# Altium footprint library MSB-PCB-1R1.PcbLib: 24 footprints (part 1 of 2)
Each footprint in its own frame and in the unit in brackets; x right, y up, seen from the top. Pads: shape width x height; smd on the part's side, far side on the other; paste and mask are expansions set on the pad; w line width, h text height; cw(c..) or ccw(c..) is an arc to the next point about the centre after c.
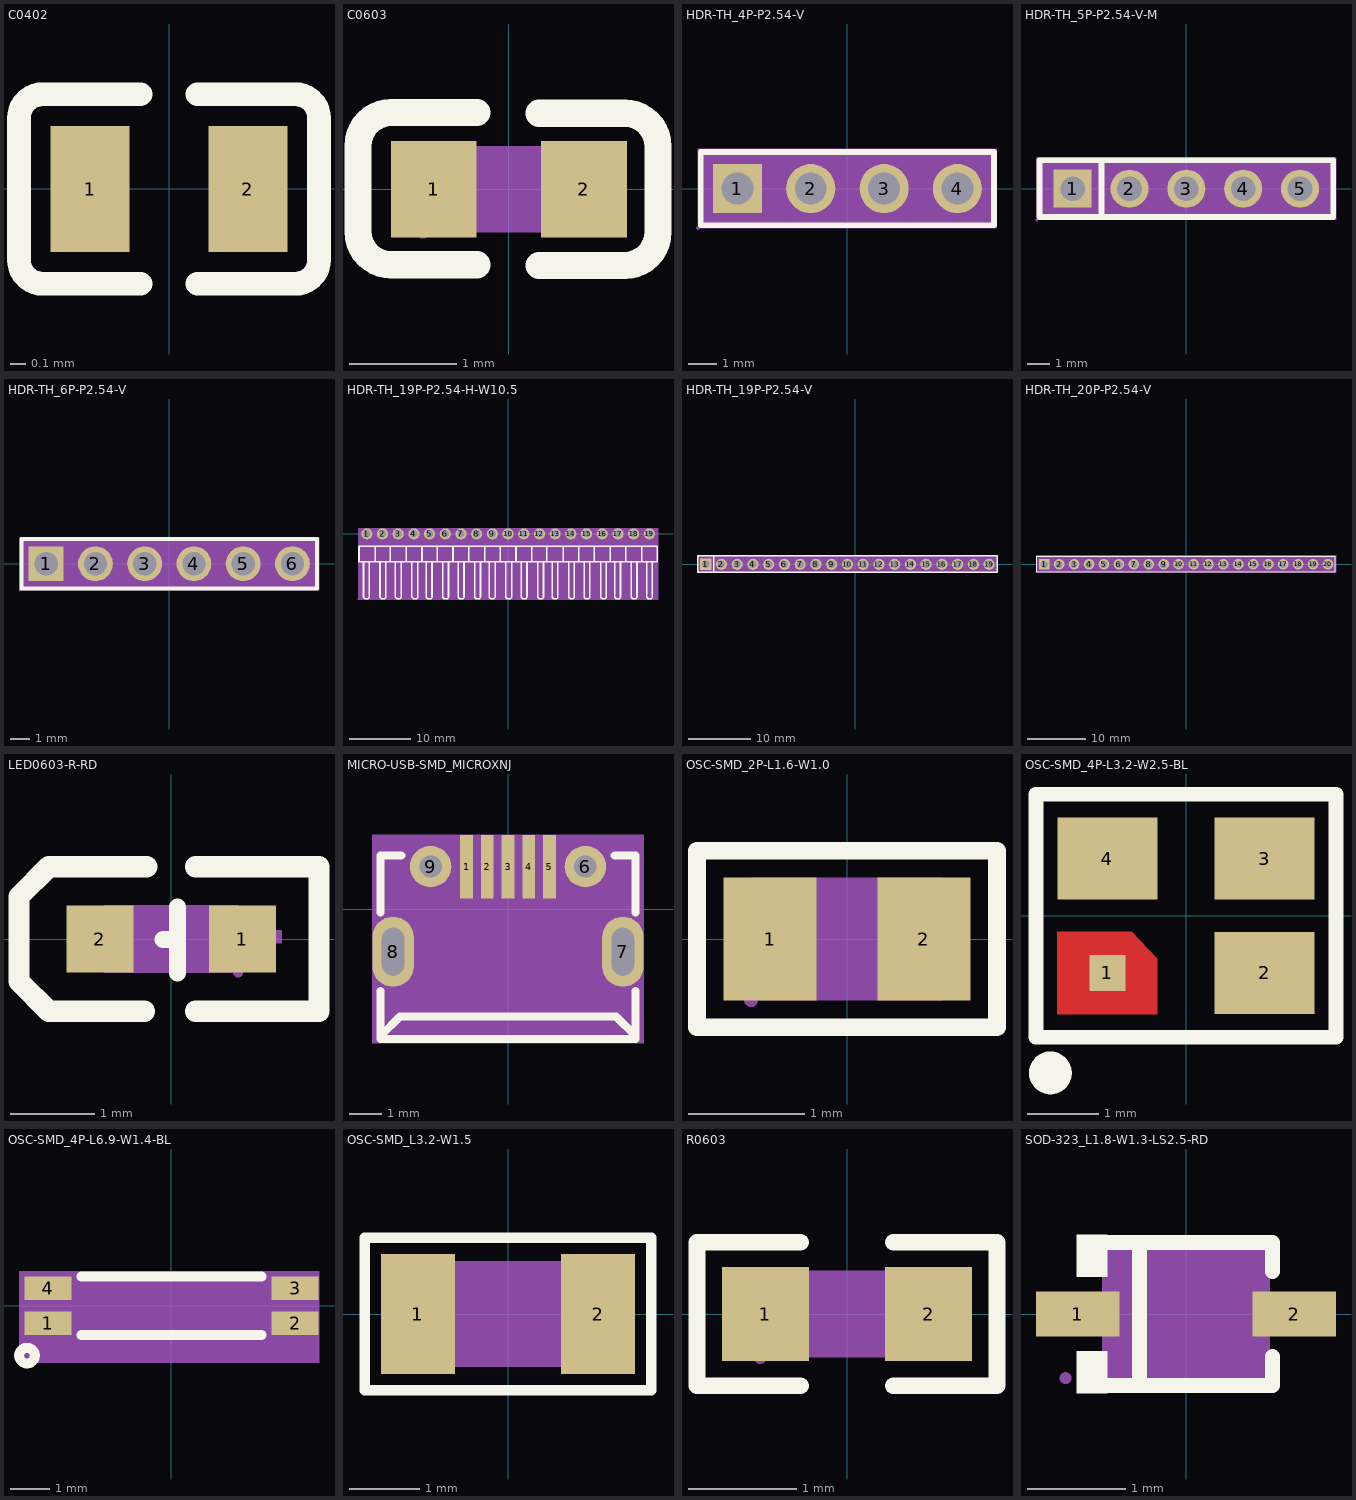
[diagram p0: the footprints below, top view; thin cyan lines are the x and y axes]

## C0402 [mm]
pads (2):
  rect 0.5x0.8 smd: 1(-0.5,0) 2(0.5,0)
Top Overlay:
  lines w0.15: -0.18,-0.6 -0.8,-0.6 cw(c-0.8,-0.45) -0.95,-0.45 -0.95,-0.4 -0.95,0.4 -0.95,0.45 cw(c-0.8,0.45) -0.8,0.6 -0.18,0.6 ; 0.18,-0.6 0.8,-0.6 ccw(c0.8,-0.45) 0.95,-0.45 0.95,-0.4 0.95,0.4 0.95,0.45 ccw(c0.8,0.45) 0.8,0.6 0.18,0.6

## C0603 [mm]
pads (2):
  rect 0.8x0.9 smd: 1(-0.7,0) 2(0.7,0)
Top Overlay:
  lines w0.254: -0.296,-0.704 -1.096,-0.704 cw(c-1.096,-0.394) -1.406,-0.394 -1.405,0.406 cw(c-1.096,0.406) -1.096,0.715 -0.296,0.715 ; 0.28,-0.71 1.08,-0.71 ccw(c1.08,-0.4) 1.39,-0.4 1.39,0.4 ccw(c1.08,0.4) 1.08,0.71 0.28,0.71
Mechanical 4:
  region: -0.8,-0.4 -0.8,0.4 0.8,0.4 0.8,-0.4
Mechanical 5:
  region: -0.8,-0.4 -0.8,0.4 -0.5,0.4 -0.5,-0.4
  region: 0.8,-0.4 0.8,0.4 0.5,0.4 0.5,-0.4
Mechanical 6:
  circle w0.06: c-0.8,-0.4 r0.03

## HDR-TH_4P-P2.54-V [mm]
pads (4):
  rect 1.7x1.7 hole 1.1: 1(-3.81,0)
  round 1.7 hole 1.1: 2(-1.27,0) 3(1.27,0) 4(3.81,0)
Top Overlay:
  lines w0.203: -5.08,-1.27 -5.08,1.27 -3.175,1.27 5.08,1.27 5.08,-1.27 -5.08,-1.27
Mechanical 4:
  region: -5.182,1.372 5.182,1.372 5.182,-1.372 -5.182,-1.372
Mechanical 5:
  circle w0.45: c3.81,0 r0.225
  circle w0.45: c1.27,0 r0.225
  circle w0.45: c-1.27,0 r0.225
  circle w0.45: c-3.81,0 r0.225
Mechanical 6:
  circle w0.06: c-5.182,-1.372 r0.03

## HDR-TH_5P-P2.54-V-M [mm]
pads (5):
  rect 1.7x1.7 hole 1.1: 1(-5.08,0)
  round 1.7 hole 1.1: 2(-2.54,0) 3(0,0) 4(2.54,0) 5(5.08,0)
Top Overlay:
  lines w0.254: -3.786,-1.27 -3.786,1.27 ; -6.56,-1.27 -6.56,1.27 6.56,1.27 6.56,-1.27 -6.56,-1.27
Mechanical 4:
  region: -6.687,1.397 6.687,1.397 6.687,-1.397 -6.687,-1.397
Mechanical 5:
  circle w0.45: c5.08,0 r0.225
  circle w0.45: c2.54,0 r0.225
  circle w0.45: c0,0 r0.225
  circle w0.45: c-2.54,0 r0.225
  circle w0.45: c-5.08,0 r0.225
Mechanical 6:
  circle w0.06: c-6.687,-1.397 r0.03

## HDR-TH_6P-P2.54-V [mm]
pads (6):
  rect 1.8x1.8 hole 1.2: 1(-6.35,0)
  round 1.8 hole 1.2: 2(-3.81,0) 3(-1.27,0) 4(1.27,0) 5(3.81,0) 6(6.35,0)
Top Overlay:
  lines w0.203: -7.62,-1.27 7.62,-1.27 7.62,1.27 -5.715,1.27 -7.62,1.27 -7.62,-1.27
Mechanical 4:
  region: -7.722,1.372 7.722,1.372 7.722,-1.372 -7.722,-1.372
Mechanical 5:
  circle w0.5: c-6.35,0 r0.25
  circle w0.5: c-3.81,0 r0.25
  circle w0.5: c-1.27,0 r0.25
  circle w0.5: c1.27,0 r0.25
  circle w0.5: c3.81,0 r0.25
  circle w0.5: c6.35,0 r0.25
Mechanical 6:
  circle w0.06: c-7.722,-1.372 r0.03

## HDR-TH_19P-P2.54-H-W10.5 [mm]
pads (19):
  round 1.8 hole 1.2: 1(-22.86,0) 2(-20.32,0) 3(-17.78,0) 4(-15.24,0) 5(-12.7,0) 6(-10.16,0) 7(-7.62,0) 8(-5.08,0) 9(-2.54,0) 10(0,0) 11(2.54,0) 12(5.08,0) 13(7.62,0) 14(10.16,0) 15(12.7,0) 16(15.24,0) 17(17.78,0) 18(20.32,0) 19(22.86,0)
Top Overlay:
  lines w0.254: -23.402,-4.5 -23.402,-10.264 -23.166,-10.5 -22.692,-10.5 -22.479,-10.287 -22.479,-4.5 ; -21.511,-4.5 -21.511,-2 ; -20.73,-4.5 -20.73,-10.264 -20.494,-10.5 ; -20.495,-10.5 -20.02,-10.5 -19.807,-10.287 -19.807,-6.54 -19.807,-4.501 ; -19.073,-4.5 -19.073,-2 ; -18.23,-4.5 -18.23,-10.264 -17.994,-10.5 -17.52,-10.5 -17.307,-10.287 -17.307,-4.5 ; -16.499,-4.5 -16.499,-2 ; -15.558,-4.5 -15.558,-10.264 -15.322,-10.5 -14.848,-10.5 -14.635,-10.287 -14.635,-4.5 ; -13.925,-4.5 -13.925,-2 ; -13.23,-4.5 -13.23,-10.264 -12.994,-10.5 -12.52,-10.5 -12.307,-10.287 -12.307,-4.5 ; -11.487,-4.5 -11.487,-2 ; -10.558,-4.5 -10.558,-10.264 -10.322,-10.5 -9.848,-10.5 -9.635,-10.287 -9.635,-6.541 -9.635,-4.501 ; -8.913,-4.5 -8.913,-2 ; -8.058,-4.5 -8.058,-10.264 -7.822,-10.5 -7.348,-10.5 -7.135,-10.287 -7.135,-4.5 ; -6.373,-4.5 -6.373,-2 ; -5.386,-4.5 -5.386,-10.264 -5.15,-10.5 -4.676,-10.5 -4.463,-10.287 -4.463,-4.5 ; -3.765,-4.5 -3.765,-2 ; -3.03,-4.5 -3.03,-10.264 -2.794,-10.5 -2.32,-10.5 -2.107,-10.287 -2.107,-4.5 ; -1.293,-4.5 -1.293,-2 ; -0.358,-4.5 -0.358,-10.264 -0.122,-10.5 0.352,-10.5 0.565,-10.287 0.565,-6.542 0.565,-4.5 ; 1.281,-4.5 1.281,-2 ; 2.142,-4.5 2.142,-10.264 2.378,-10.5 2.852,-10.5 3.065,-10.287 3.065,-4.5 ; 3.855,-4.5 3.855,-2 ; 4.814,-4.5 4.814,-10.264 5.05,-10.5 5.524,-10.5 5.737,-10.287 5.737,-4.5 ; 6.293,-4.5 6.293,-2 ; 7.142,-4.5 7.142,-10.264 7.378,-10.5 7.852,-10.5 8.065,-10.287 8.065,-4.5 ; 8.901,-4.5 8.901,-2 ; 9.814,-4.5 9.814,-10.264 10.05,-10.5 ; 10.049,-10.5 10.524,-10.5 10.737,-10.287 10.737,-6.54 10.737,-4.501 ; 11.475,-4.5 11.475,-2 ; 12.314,-4.5 12.314,-10.264 12.55,-10.5 13.024,-10.5 13.237,-10.287 13.237,-4.5 ; 13.981,-4.5 13.981,-2 ; 14.986,-4.5 14.986,-10.264 15.222,-10.5 15.697,-10.5 15.91,-10.287 15.91,-4.5 ; 16.555,-4.5 16.555,-2 ; 17.27,-4.5 17.27,-10.264 17.506,-10.5 17.98,-10.5 18.193,-10.287 18.193,-4.5 ; 19.027,-4.5 19.027,-2 ; 19.942,-4.5 19.942,-10.264 20.178,-10.5 ; 20.865,-4.501 20.865,-6.54 ; 21.635,-4.5 21.635,-2 ; 22.442,-4.5 22.442,-10.264 22.678,-10.5 23.152,-10.5 23.365,-10.287 23.365,-4.5 ; 24.13,-4.5 -24.13,-4.5 -24.13,-2 24.13,-2 ; 24.141,-4.5 24.141,-2 ; 20.652,-10.5 20.177,-10.5 20.652,-10.5 ; 20.652,-10.5 20.865,-10.287 ; 20.652,-10.5 20.865,-10.287 ; 20.865,-10.287 20.865,-6.54 ; 20.865,-10.287 20.865,-6.54
Mechanical 4:
  region: -24.257,0.9 24.268,0.9 24.268,-10.627 -24.257,-10.627
Mechanical 5:
  circle w0.5: c-22.86,0 r0.25
  circle w0.5: c-20.32,0 r0.25
  circle w0.5: c-17.78,0 r0.25
  circle w0.5: c-15.24,0 r0.25
  circle w0.5: c-12.7,0 r0.25
  circle w0.5: c-10.16,0 r0.25
  circle w0.5: c-7.62,0 r0.25
  circle w0.5: c-5.08,0 r0.25
  circle w0.5: c-2.54,0 r0.25
  circle w0.5: c0,0 r0.25
  circle w0.5: c2.54,0 r0.25
  circle w0.5: c5.08,0 r0.25
  circle w0.5: c7.62,0 r0.25
  circle w0.5: c10.16,0 r0.25
  circle w0.5: c12.7,0 r0.25
  circle w0.5: c15.24,0 r0.25
  circle w0.5: c17.78,0 r0.25
  circle w0.5: c20.32,0 r0.25
  circle w0.5: c22.86,0 r0.25
Mechanical 6:
  circle w0.06: c-24.257,-10.627 r0.03

## HDR-TH_19P-P2.54-V [mm]
pads (19):
  rect 1.8x1.8 hole 1.2: 1(-24.13,0)
  round 1.8 hole 1.2: 2(-21.59,0) 3(-19.05,0) 4(-16.51,0) 5(-13.97,0) 6(-11.43,0) 7(-8.89,0) 8(-6.35,0) 9(-3.81,0) 10(-1.27,0) 11(1.27,0) 12(3.81,0) 13(6.35,0) 14(8.89,0) 15(11.43,0) 16(13.97,0) 17(16.51,0) 18(19.05,0) 19(21.59,0)
Top Overlay:
  lines w0.203: -22.86,-1.27 -22.86,1.397 ; -25.4,-1.27 -25.4,1.397 22.86,1.397 22.86,0.635 22.86,-1.27 -25.4,-1.27
Mechanical 4:
  region: -25.502,1.499 22.86,1.499 22.86,-1.372 -25.502,-1.372
Mechanical 5:
  circle w0.5: c21.59,0 r0.25
  circle w0.5: c19.05,0 r0.25
  circle w0.5: c16.51,0 r0.25
  circle w0.5: c13.97,0 r0.25
  circle w0.5: c11.43,0 r0.25
  circle w0.5: c8.89,0 r0.25
  circle w0.5: c6.35,0 r0.25
  circle w0.5: c3.81,0 r0.25
  circle w0.5: c1.27,0 r0.25
  circle w0.5: c-1.27,0 r0.25
  circle w0.5: c-3.81,0 r0.25
  circle w0.5: c-6.35,0 r0.25
  circle w0.5: c-8.89,0 r0.25
  circle w0.5: c-11.43,0 r0.25
  circle w0.5: c-13.97,0 r0.25
  circle w0.5: c-16.51,0 r0.25
  circle w0.5: c-19.05,0 r0.25
  circle w0.5: c-21.59,0 r0.25
  circle w0.5: c-24.13,0 r0.25
Mechanical 6:
  circle w0.06: c-25.502,-1.372 r0.03

## HDR-TH_20P-P2.54-V [mm]
pads (20):
  rect 1.8x1.8 hole 1.2: 1(-24.13,0)
  round 1.8 hole 1.2: 2(-21.59,0) 3(-19.05,0) 4(-16.51,0) 5(-13.97,0) 6(-11.43,0) 7(-8.89,0) 8(-6.35,0) 9(-3.81,0) 10(-1.27,0) 11(1.27,0) 12(3.81,0) 13(6.35,0) 14(8.89,0) 15(11.43,0) 16(13.97,0) 17(16.51,0) 18(19.05,0) 19(21.59,0) 20(24.13,0)
Top Overlay:
  lines w0.203: -25.4,-1.27 25.4,-1.27 25.4,1.27 25.4,1.397 -25.4,1.397 -25.4,-1.27
Mechanical 4:
  region: -25.502,1.499 25.502,1.499 25.502,-1.372 -25.502,-1.372
Mechanical 5:
  circle w0.5: c-24.13,0 r0.25
  circle w0.5: c-21.59,0 r0.25
  circle w0.5: c-19.05,0 r0.25
  circle w0.5: c-16.51,0 r0.25
  circle w0.5: c-13.97,0 r0.25
  circle w0.5: c-11.43,0 r0.25
  circle w0.5: c-8.89,0 r0.25
  circle w0.5: c-6.35,0 r0.25
  circle w0.5: c-3.81,0 r0.25
  circle w0.5: c-1.27,0 r0.25
  circle w0.5: c1.27,0 r0.25
  circle w0.5: c3.81,0 r0.25
  circle w0.5: c6.35,0 r0.25
  circle w0.5: c8.89,0 r0.25
  circle w0.5: c11.43,0 r0.25
  circle w0.5: c13.97,0 r0.25
  circle w0.5: c16.51,0 r0.25
  circle w0.5: c19.05,0 r0.25
  circle w0.5: c21.59,0 r0.25
  circle w0.5: c24.13,0 r0.25
Mechanical 6:
  circle w0.06: c-25.502,-1.372 r0.03

## LED0603-R-RD [mm]
pads (2):
  rect 0.8x0.8 smd: 1(0.851,0) 2(-0.851,0)
Top Overlay:
  lines w0.203: -0.099,-0.008 0.076,-0.008 ; 0.076,-0.406 0.076,0.381
  lines w0.254: -0.318,-0.864 -1.46,-0.864 -1.816,-0.508 -1.816,0.508 -1.46,0.864 -0.292,0.864 ; 0.292,-0.864 1.765,-0.864 1.765,0.864 0.292,0.864
Mechanical 4:
  region: -0.8,0.4 0.8,0.4 0.8,-0.4 -0.8,-0.4
Mechanical 5:
  region: 0.8,0.4 0.8,-0.4 0.5,-0.4 0.5,0.4
  region: -0.8,-0.4 -0.8,0.4 -0.5,0.4 -0.5,-0.4
Mechanical 6:
  circle w0.06: c0.8,-0.4 r0.03
Mechanical 15:
  region: 0.66,0.102 1.321,0.102 1.321,-0.051 0.66,-0.051
  region: 0.936,-0.275 0.936,0.385 1.088,0.385 1.088,-0.275
  region: -1.193,0.05 -0.533,0.05 -0.533,-0.103 -1.193,-0.103

## MICRO-USB-SMD_MICROXNJ [mm]
pads (9):
  rect 0.4x2 smd mask+0: 1(-1.3,1.327) 2(-0.65,1.327) 3(0,1.327) 4(0.65,1.327) 5(1.3,1.327)
  round 1.3 hole 0.7: 6(2.425,1.335) 9(-2.425,1.335)
  oval 1.3x2.2 hole 0.7 slot 1.5 at 90 deg: 7(3.6,-1.335) 8(-3.6,-1.335)
Top Overlay:
  lines w0.254: -4,-4.073 4,-4.073 4,-2.57 ; -4,-4.052 -4,-2.57 ; -4,-0.1 -4,1.677 -3.344,1.677 ; -3.97,-4.052 -3.97,-3.953 -3.38,-3.363 3.39,-3.363 3.98,-3.953 3.98,-4.073 ; 3.344,1.677 4,1.677 4,-0.1
Mechanical 4:
  region: -4.25,2.328 4.25,2.328 4.25,-4.2 -4.25,-4.2
Mechanical 5:
  region: 1.1,2.327 1.5,2.327 1.5,0.327 1.1,0.327
  region: 0.45,2.327 0.85,2.327 0.85,0.327 0.45,0.327
  region: -0.2,2.327 0.2,2.327 0.2,0.327 -0.2,0.327
  region: -0.85,2.327 -0.45,2.327 -0.45,0.327 -0.85,0.327
  region: -1.5,2.327 -1.1,2.327 -1.1,0.327 -1.5,0.327

## OSC-SMD_2P-L1.6-W1.0 [mm]
pads (2):
  rect 0.8x1.06 smd: 1(-0.66,0) 2(0.66,0)
Top Overlay:
  lines w0.152: -1.289,-0.759 1.289,-0.759 1.289,0.759 -1.289,0.759 -1.289,-0.759
Mechanical 4:
  region: -0.825,-0.525 -0.825,0.525 0.825,0.525 0.825,-0.525
Mechanical 5:
  region: 0.36,-0.43 0.36,0.43 0.76,0.43 0.76,-0.43
  region: -0.36,-0.43 -0.36,0.43 -0.76,0.43 -0.76,-0.43
Mechanical 6:
  circle w0.06: c-0.825,-0.525 r0.03

## OSC-SMD_4P-L3.2-W2.5-BL [mm]
pads (4):
  rect 0.508x0.508 smd: 1(-1.1,-0.8)
  rect 1.4x1.15 smd: 2(1.1,-0.8) 3(1.1,0.8) 4(-1.1,0.8)
Top Layer:
  region: -1.8,-0.225 -0.762,-0.225 -0.4,-0.604 -0.4,-1.375 -1.8,-1.375
Top Overlay:
  lines w0.203: -2.1,-1.7 -2.1,1.7 2.1,1.7 2.1,-1.7 -2.1,-1.7
  lines w0.3: -1.9,-2.05 ccw(c-1.899,-2.2) -1.897,-2.05
Top Paste:
  region: -1.8,-0.225 -0.762,-0.225 -0.4,-0.604 -0.4,-1.375 -1.8,-1.375
Top Solder:
  region: -1.8,-0.225 -0.762,-0.225 -0.4,-0.604 -0.4,-1.375 -1.8,-1.375

## OSC-SMD_4P-L6.9-W1.4-BL [mm]
pads (4):
  rect 1.2x0.6 smd: 1(-3.15,-0.45) 2(3.15,-0.45) 3(3.15,0.45) 4(-3.15,0.45)
Top Overlay:
  circle w0.254: c-3.683,-1.27 r0.2
  lines w0.254: -2.3,-0.75 2.3,-0.75 ; -2.3,0.75 2.3,0.75
Mechanical 4:
  region: -3.886,0.877 3.759,0.877 3.759,-1.448 -3.886,-1.448
Mechanical 5:
  region: -3.75,-0.15 -2.55,-0.15 -2.55,-0.75 -3.75,-0.75
  region: 2.55,-0.15 3.75,-0.15 3.75,-0.75 2.55,-0.75
  region: 2.55,0.75 3.75,0.75 3.75,0.15 2.55,0.15
  region: -3.75,0.75 -2.55,0.75 -2.55,0.15 -3.75,0.15

## OSC-SMD_L3.2-W1.5 [mm]
pads (2):
  rect 1.05x1.7 smd: 1(-1.275,0) 2(1.275,0)
Top Overlay:
  lines w0.152: -2.029,-1.079 2.029,-1.079 2.029,1.079 -2.029,1.079 -2.029,-1.079
Mechanical 4:
  region: -1.6,-0.75 -1.6,0.75 1.6,0.75 1.6,-0.75
Mechanical 5:
  region: 0.85,-0.75 0.85,0.75 1.5,0.75 1.5,-0.75
  region: -0.85,-0.75 -0.85,0.75 -1.5,0.75 -1.5,-0.75
Mechanical 6:
  circle w0.06: c-1.6,-0.75 r0.03

## R0603 [mm]
pads (2):
  rect 0.806x0.864 smd: 1(-0.753,0) 2(0.753,0)
Top Overlay:
  lines w0.152: -0.426,-0.661 -1.385,-0.661 -1.385,0.661 -0.426,0.661 ; 0.426,-0.661 1.385,-0.661 1.385,0.661 0.426,0.661
Top Paste:
  region: 1.195,0.45 0.395,0.45 0.345,0.4 0.345,0.172 0.715,0.172 0.715,-0.158 0.345,-0.158 0.345,-0.4 0.395,-0.45 1.195,-0.45 1.245,-0.4 1.245,0.4
  region: -0.355,0.4 -0.355,0.172 -0.735,0.172 -0.735,-0.158 -0.355,-0.158 -0.355,-0.4 -0.405,-0.45 -1.195,-0.45 -1.245,-0.4 -1.245,0.4 -1.195,0.45 -0.405,0.45
Mechanical 4:
  region: -0.8,-0.4 -0.8,0.4 0.8,0.4 0.8,-0.4
Mechanical 5:
  region: -0.8,-0.4 -0.8,0.4 -0.5,0.4 -0.5,-0.4
  region: 0.8,-0.4 0.8,0.4 0.5,0.4 0.5,-0.4
Mechanical 6:
  circle w0.06: c-0.8,-0.4 r0.03

## SOD-323_L1.8-W1.3-LS2.5-RD [mm]
pads (2):
  rect 0.845x0.455 smd: 1(-1.098,0) 2(1.098,0)
Top Overlay:
  region: -0.8,0.802 -0.8,0.38 -1.105,0.38 -1.105,0.802
  region: -0.8,-0.802 -0.8,-0.38 -1.105,-0.38 -1.105,-0.802
  lines w0.152: -0.876,-0.726 0.876,-0.726 0.876,-0.431 ; -0.876,0.726 0.876,0.726 0.876,0.431 ; -0.472,-0.726 -0.472,0.726
Mechanical 4:
  region: 0.85,0.65 0.85,-0.65 -0.85,-0.65 -0.85,0.65
Mechanical 5:
  pour cut-out: -0.84,0.16 -0.84,-0.16 -0.96,-0.16 -0.96,0.16
  region: -0.95,0.16 -0.95,-0.16 -1.25,-0.16 -1.25,0.16
  pour cut-out: 0.96,0.16 0.96,-0.16 0.84,-0.16 0.84,0.16
  region: 1.25,0.16 1.25,-0.16 0.95,-0.16 0.95,0.16
Mechanical 6:
  circle w0.06: c-1.22,-0.65 r0.03
Mechanical 15:
  region: -0.644,0.078 -0.644,-0.078 -0.02,-0.078 -0.02,0.078
  region: 0.644,0.078 0.644,-0.078 0.02,-0.078 0.02,0.078
  region: 0.41,0.52 0.41,-0.52 0.254,-0.52 0.254,0.52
